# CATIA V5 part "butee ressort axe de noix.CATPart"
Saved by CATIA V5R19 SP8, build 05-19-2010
Part number: butee ressort axe de noix
Revision: ANY
Definition: UNKNOWN
Nomenclature: butee ressort axe de noix
Source: Unknown
Bounding box of the stored display mesh (mm): x -8.69 to 8.69, y 14.593 to 19, z -5.3 to 5.3
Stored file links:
  D:\Documents\1_Travail\1 - ac-limoges.fr\ac-limoges.fr\Emmanuel Maynard - STI2D_Turgot\2 -2I2D\2_SEQUENCE_Serrure_Biométrique\5-Spé_ITEC\Serrure_Bio_Eleve\butee ressort axe de noix.CATPart
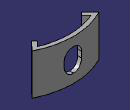
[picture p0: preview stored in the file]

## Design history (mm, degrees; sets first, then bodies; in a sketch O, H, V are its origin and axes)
Body1 "Enlèv. mat.-Extru.1" (main body)
  Solid1: solid without history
